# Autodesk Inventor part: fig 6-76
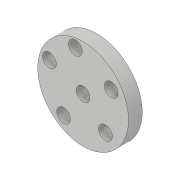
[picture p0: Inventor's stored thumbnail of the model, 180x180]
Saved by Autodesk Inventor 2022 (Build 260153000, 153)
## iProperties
Created: 2018-03
Part Number: fig 6-76
Material: Generic
Document SubType Name: Modeling
Designer: CADCIM 00
Density: 1 g/cm^3
Appearance: Default
Author: CADCIM 00
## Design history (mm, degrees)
sketch "Sketch1"
  geometry: C1 r 16.506 at (0, 0); 1 further point
  constraints: 1 centre point, 1 coincident
extrude "Extrusion1" new body sketch "Sketch1" distance "d0" = 5; taper "d1" = 0 deg
sketch "Sketch3"
  geometry: 2 further points
  constraints: 1 coincident
hole "Hole1" sketch "Sketch3" at (0, 0) diameter "d2" = 5; stored, may be unused: countersink angle "d6" = 90 deg, drill point angle "d8" = 118 deg; dims "d3" = 6, "d4" = 4, "d5" = 2, "d7" = 8
sketch "Sketch2"
  geometry: 6 further points
feature "Sketch Driven Pattern1" sketch "Sketch2"
body "Solid1"
